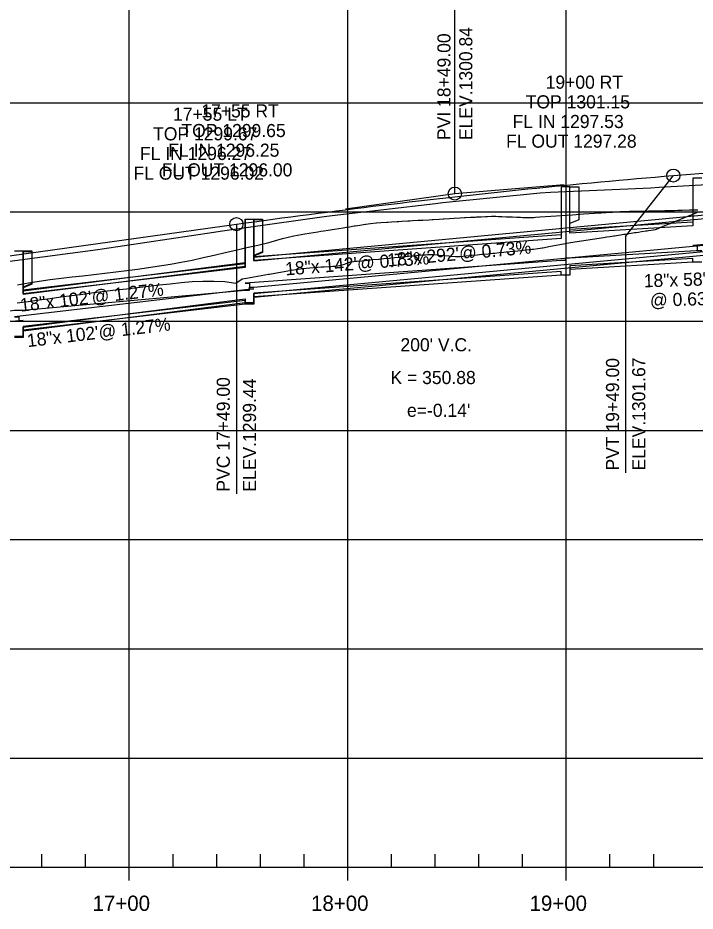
# Model space of a CAD drawing. Extents: x 670877 to 686811, y 705985 to 708501.
# Drawn here: x 685126.3 to 685436.3, y 707872.7 to 708281.7 of the extents above; entities that cross this region are included whole.
import ezdxf

# ---------------------------------------------------------------- set-up
doc = ezdxf.new("R2010")
doc.units = 0
for name, color, linetype in [('30', 7, 'Continuous'), ('37', 7, 'Continuous'), ('DRAINAGE_HGL LEFT', 7, 'Continuous'), ('DRAINAGE_HGL RIGHT', 7, 'Continuous'), ('Profile Drainage Annot Left', 7, 'Continuous'), ('Profile Drainage Annot Right', 7, 'Continuous'), ('R_Drainage Extensions_LEFT', 7, 'Continuous'), ('R_Drainage Extensions_RIGHT', 7, 'Continuous'), ('R_Drainage LEFT', 7, 'Continuous'), ('R_Drainage RIGHT', 7, 'Continuous'), ('R_Exist Surface', 7, 'Continuous'), ('R_Profile Work Left', 7, 'Continuous'), ('R_Profile Work Right', 7, 'Continuous'), ('R_Vert Alg', 7, 'Continuous'), ('R_Vert Alg Annot', 7, 'Continuous')]:
    doc.layers.add(name, color=color, linetype=linetype)

msp = doc.modelspace()

# ---------------------------------------------------------------- linework, layer by layer
at = {"layer": '37'}
for p, q in [((685177.28, 707892.85), (685177.28, 708492.85)), ((685277.28, 707892.85), (685277.28, 708492.85)), ((685377.28, 707892.85), (685377.28, 708492.85)), ((684477.28, 708242.85), (686777.28, 708242.85)), ((684477.28, 708192.85), (686777.28, 708192.85)), ((684477.28, 708142.85), (686777.28, 708142.85)), ((684477.28, 708092.85), (686777.28, 708092.85)), ((684477.28, 708042.85), (686777.28, 708042.85)), ((684477.28, 707992.85), (686777.28, 707992.85)), ((684477.28, 707942.85), (686777.28, 707942.85)), ((685137.28, 707892.85), (685137.28, 707898.85)), ((685157.28, 707892.85), (685157.28, 707898.85)), ((685197.28, 707892.85), (685197.28, 707898.85)), ((685217.28, 707892.85), (685217.28, 707898.85)), ((685237.28, 707892.85), (685237.28, 707898.85)), ((685257.28, 707892.85), (685257.28, 707898.85)), ((685297.28, 707892.85), (685297.28, 707898.85)), ((685317.28, 707892.85), (685317.28, 707898.85)), ((685337.28, 707892.85), (685337.28, 707898.85)), ((685357.28, 707892.85), (685357.28, 707898.85)), ((685397.28, 707892.85), (685397.28, 707898.85)), ((685417.28, 707892.85), (685417.28, 707898.85)), ((684477.28, 707892.85), (686777.28, 707892.85)), ((685177.28, 707886.85), (685177.28, 707892.85)), ((685277.28, 707886.85), (685277.28, 707892.85)), ((685377.28, 707886.85), (685377.28, 707892.85))]:
    msp.add_line(p, q, dxfattribs=at)
at = {"layer": 'DRAINAGE_HGL LEFT'}
msp.add_lwpolyline([(684855.2, 708111.48), (684875.01, 708112.97), (684877.28, 708112.97), (684877.28, 708115), (684879.28, 708115), (685124.73, 708147.9), (685126.73, 708147.9), (685126.73, 708147.9), (685128.73, 708147.9), (685230.25, 708157.07), (685232.25, 708157.07), (685232.25, 708158.42), (685234.25, 708158.42), (685525.17, 708185.62), (685527.18, 708185.62), (685527.18, 708186.58), (685529.23, 708186.58), (685617.8, 708197.78), (685619.52, 708197.78)], dxfattribs=at)
at = {"layer": 'DRAINAGE_HGL RIGHT'}
msp.add_lwpolyline([(685566.98, 708188.74), (685568.98, 708188.74), (685568.98, 708188.74), (685565, 708188.74), (685435.23, 708177.54), (685437.24, 708177.54), (685437.24, 708175.27), (685439.26, 708175.27), (685378.95, 708171.67), (685376.97, 708171.67), (685376.97, 708170.59), (685375, 708170.59), (685230.25, 708160.29), (685232.25, 708160.29), (685232.25, 708157.7), (685234.25, 708157.7), (685124.73, 708144.8), (685126.73, 708144.8), (685126.73, 708143.15), (685128.73, 708143.15), (684875.28, 708121.55)], dxfattribs=at)
at = {"layer": 'R_Drainage Extensions_LEFT'}
for points in [[(685234.25, 708189.55), (685238.25, 708189.55), (685238.25, 708174.55), (685234.25, 708172.88), (685234.25, 708189.55)], [(685128.73, 708175.11), (685132.73, 708175.11), (685132.73, 708160.11), (685128.73, 708158.45), (685128.73, 708175.11)]]:
    msp.add_lwpolyline(points, dxfattribs=at)
at = {"layer": 'R_Drainage Extensions_RIGHT'}
for points in [[(685378.97, 708204.29), (685382.97, 708204.29), (685382.97, 708189.29), (685378.97, 708187.63), (685378.97, 708204.29)], [(685234.25, 708189.35), (685238.25, 708189.35), (685238.25, 708174.35), (685234.25, 708172.68), (685234.25, 708189.35)], [(685128.73, 708174.81), (685132.73, 708174.81), (685132.73, 708159.81), (685128.73, 708158.15), (685128.73, 708174.81)]]:
    msp.add_lwpolyline(points, dxfattribs=at)
at = {"layer": 'R_Drainage LEFT'}
for points in [[(685234.25, 708172.21), (685525.15, 708199.41)], [(685234.25, 708170.55), (685525.15, 708197.75)], [(685230.25, 708168.05), (685230.25, 708189.55)], [(685230.25, 708189.55), (685234.25, 708189.55)], [(685234.25, 708189.55), (685234.25, 708170.55)], [(685234.25, 708155.55), (685525.15, 708182.75)], [(685234.25, 708153.88), (685525.15, 708181.08)], [(685124.73, 708175.11), (685128.73, 708175.11)], [(685128.73, 708175.11), (685128.73, 708155.15)], [(685128.73, 708156.81), (685230.25, 708169.71)], [(685128.73, 708155.15), (685230.25, 708168.05)], [(685128.73, 708140.15), (685230.25, 708153.05)], [(685230.25, 708153.05), (685230.25, 708151.38)], [(685234.25, 708151.38), (685234.25, 708155.55)], [(685128.73, 708138.48), (685230.25, 708151.38)], [(685230.25, 708151.38), (685234.25, 708151.38)], [(685128.73, 708135.98), (685128.73, 708140.15)], [(685124.73, 708135.98), (685128.73, 708135.98)]]:
    msp.add_lwpolyline(points, dxfattribs=at)
at = {"layer": 'R_Drainage RIGHT'}
for points in [[(685439.25, 708208.25), (685435.23, 708208.25)], [(685435.23, 708208.25), (685435.23, 708186.51)], [(685378.97, 708204.35), (685374.97, 708204.35)], [(685374.97, 708204.35), (685374.97, 708180.65)], [(685378.97, 708183.15), (685378.97, 708204.35)], [(685234.25, 708189.35), (685230.25, 708189.35)], [(685230.25, 708189.35), (685230.25, 708167.38)], [(685234.25, 708170.63), (685234.25, 708189.35)], [(685435.23, 708188.17), (685378.97, 708184.82)], [(685435.23, 708186.51), (685378.97, 708183.15)], [(685374.97, 708182.31), (685234.25, 708172.3)], [(685374.97, 708180.65), (685234.25, 708170.63)], [(685128.73, 708174.95), (685124.73, 708174.95)], [(685128.73, 708155.42), (685128.73, 708174.95)], [(685230.25, 708169.04), (685128.73, 708157.09)], [(685435.23, 708171.51), (685378.97, 708168.15)], [(685435.23, 708169.84), (685378.97, 708166.48)], [(685435.23, 708169.84), (685435.23, 708171.51)], [(685439.25, 708169.84), (685435.23, 708169.84)], [(685230.25, 708167.38), (685128.73, 708155.42)], [(685374.97, 708165.65), (685234.25, 708155.63)], [(685374.97, 708163.98), (685374.97, 708165.65)], [(685378.97, 708168.15), (685378.97, 708163.98)], [(685374.97, 708163.98), (685234.25, 708153.97)], [(685378.97, 708163.98), (685374.97, 708163.98)], [(685230.25, 708152.38), (685128.73, 708140.42)], [(685230.25, 708150.71), (685230.25, 708152.38)], [(685234.25, 708155.63), (685234.25, 708150.71)], [(685230.25, 708150.71), (685128.73, 708138.75)], [(685234.25, 708150.71), (685230.25, 708150.71)], [(685128.73, 708140.42), (685128.73, 708135.44)], [(685128.73, 708135.44), (685124.73, 708135.44)]]:
    msp.add_lwpolyline(points, dxfattribs=at)
at = {"layer": 'R_Exist Surface'}
msp.add_lwpolyline([(685112.1, 708168.96), (685162.81, 708175.65), (685164.92, 708175.96), (685215.99, 708183.62), (685218.83, 708184.02), (685266.46, 708190.74), (685270.16, 708191.22), (685317.41, 708196.75), (685320.79, 708197.2), (685365.31, 708201.6), (685370, 708201.88), (685416.05, 708203.83), (685419.8, 708204.14), (685461.21, 708206.48), (685467.7, 708207.16), (685497.2, 708211.08), (685499, 708211.2), (685550.57, 708215), (685552.14, 708215.26), (685552.65, 708215.45), (685556.89, 708215.85), (685597.33, 708219.75), (685604.44, 708220.24), (685639.36, 708224.31)], dxfattribs=at)
at = {"layer": 'R_Profile Work Left'}
msp.add_lwpolyline([(685126, 708151.29), (685131, 708151.92), (685136, 708152.59), (685141, 708153.26), (685146, 708153.93), (685151, 708154.59), (685156, 708155.26), (685161, 708155.93), (685166, 708156.56), (685171, 708157.14), (685176, 708157.72), (685181, 708158.29), (685186, 708158.87), (685191, 708159.45), (685196, 708160.02), (685201, 708160.6), (685206, 708161.06), (685211, 708161.1), (685215.99, 708161.14), (685220.99, 708161.07), (685225.98, 708160.26), (685228.99, 708162.2), (685230.99, 708162.56), (685235.99, 708163.44), (685240.99, 708164.33), (685240.99, 708164.33), (685241.29, 708164.38), (685241.51, 708164.41), (685241.51, 708164.42), (685242.28, 708164.55), (685246.51, 708165.29), (685251.51, 708166.16), (685256.51, 708167.04), (685261.51, 708167.46), (685261.51, 708167.46), (685263.62, 708167.6), (685265.1, 708167.69), (685266.51, 708167.78), (685268.63, 708167.92), (685270.42, 708168.03), (685271.51, 708168.1), (685273.65, 708168.3), (685275.73, 708169.01), (685276.51, 708169.27), (685277.28, 708169.54), (685278.66, 708170.01), (685281.04, 708170.3), (685281.51, 708170.34), (685283.68, 708170.55), (685286.35, 708170.8), (685286.51, 708170.81), (685288.69, 708171.02), (685291.51, 708171.28), (685291.66, 708171.3), (685293.7, 708171.49), (685296.51, 708171.75), (685296.97, 708171.8), (685298.71, 708171.96), (685301.51, 708172.22), (685302.27, 708172.29), (685303.72, 708172.43), (685306.51, 708172.69), (685307.57, 708172.79), (685308.72, 708172.9), (685311.51, 708173.16), (685312.87, 708173.29), (685313.72, 708173.37), (685316.51, 708173.32), (685318.16, 708173.17), (685318.72, 708173.12), (685321.51, 708172.87), (685323.45, 708172.7), (685323.72, 708172.67), (685326.51, 708172.43), (685328.71, 708172.46), (685328.74, 708172.46), (685331.51, 708172.74), (685333.69, 708172.96), (685334.02, 708173), (685336.51, 708173.25), (685338.68, 708173.46), (685339.3, 708173.53), (685341.51, 708173.75), (685343.65, 708173.96), (685344.57, 708174.06), (685346.51, 708174.25), (685348.63, 708174.47), (685349.84, 708174.59), (685351.51, 708174.76), (685353.59, 708174.96), (685355.1, 708175.12), (685356.51, 708175.26), (685358.55, 708175.46), (685360.36, 708175.65), (685361.51, 708175.76), (685362.28, 708175.84), (685364.28, 708176.05), (685365.28, 708176.24), (685366.28, 708176.42), (685366.51, 708176.47), (685367.28, 708176.61), (685369.28, 708176.98), (685374.28, 708177.9), (685379.28, 708178.83), (685384.28, 708179.67), (685389.28, 708180.44), (685394.28, 708181.2), (685395.79, 708181.43), (685397.28, 708181.66), (685398.97, 708181.92), (685399.28, 708181.96), (685400.34, 708182.13), (685402.16, 708182.4), (685403.69, 708182.64), (685404.28, 708182.73), (685405.35, 708182.89), (685407.04, 708183.15), (685408.55, 708183.38), (685409.28, 708183.49), (685410.4, 708183.66), (685411.75, 708183.87), (685413.76, 708184.18), (685414.28, 708184.26), (685414.95, 708184.36), (685417.13, 708184.69), (685418.16, 708184.87), (685419.28, 708185.32), (685420.5, 708185.82), (685421.37, 708186.18), (685423.87, 708187.2), (685424.28, 708187.36), (685424.58, 708187.49), (685426.28, 708188.18), (685427.25, 708188.57), (685427.8, 708188.8), (685429.28, 708189.4), (685430.63, 708189.95), (685431.01, 708190.11), (685434.01, 708191.33), (685434.23, 708191.42), (685434.28, 708191.44), (685434.28, 708191.44), (685437.39, 708192.7)], dxfattribs=at)
at = {"layer": 'R_Profile Work Right'}
msp.add_lwpolyline([(685126.08, 708159.52), (685131.08, 708160.33), (685136.08, 708161.14), (685141.08, 708161.91), (685146.08, 708162.5), (685151.08, 708163.09), (685156.08, 708163.68), (685161.08, 708164.27), (685166.08, 708164.86), (685171.08, 708165.45), (685176.07, 708166.04), (685181.07, 708166.7), (685186.07, 708167.41), (685191.07, 708168.13), (685196.08, 708168.97), (685201.08, 708169.82), (685206.08, 708170.82), (685211.08, 708171.96), (685216.08, 708173.11), (685221.08, 708174.25), (685226.09, 708175.39), (685229.09, 708176.08), (685231.09, 708176.53), (685236.09, 708177.68), (685241.09, 708178.82), (685241.09, 708178.83), (685242.23, 708179.11), (685247.38, 708180.74), (685252.52, 708181.98), (685257.64, 708182.83), (685257.64, 708182.83), (685263.54, 708183.77), (685264.97, 708184), (685266.32, 708184.22), (685268.36, 708184.55), (685270.07, 708184.83), (685271.12, 708185), (685273.17, 708185.33), (685275.17, 708185.65), (685275.92, 708185.77), (685276.66, 708185.89), (685277.99, 708186.1), (685280.27, 708186.46), (685280.72, 708186.53), (685282.8, 708186.86), (685285.37, 708187.27), (685285.52, 708187.29), (685287.62, 708187.62), (685290.32, 708187.92), (685290.47, 708187.93), (685292.43, 708188.05), (685295.12, 708188.21), (685295.56, 708188.24), (685297.23, 708188.34), (685299.92, 708188.49), (685300.65, 708188.54), (685302.04, 708188.62), (685304.71, 708188.77), (685305.73, 708188.83), (685306.83, 708188.89), (685309.5, 708189.04), (685310.81, 708189.12), (685311.63, 708189.16), (685314.3, 708189.31), (685315.88, 708189.39), (685316.42, 708189.42), (685319.09, 708189.57), (685320.96, 708189.66), (685321.21, 708189.68), (685323.88, 708189.84), (685325.99, 708189.97), (685326.02, 708189.97), (685328.68, 708190.13), (685330.77, 708190.25), (685331.09, 708190.27), (685333.47, 708190.4), (685335.55, 708190.52), (685336.15, 708190.56), (685338.26, 708190.68), (685340.32, 708190.79), (685341.2, 708190.84), (685343.06, 708190.94), (685345.08, 708190.87), (685346.24, 708190.82), (685347.83, 708190.76), (685349.82, 708190.68), (685351.27, 708190.63), (685352.61, 708190.57), (685354.56, 708190.49), (685356.32, 708190.42), (685357.44, 708190.38), (685358.19, 708190.35), (685360.18, 708190.26), (685361.18, 708190.28), (685362.18, 708190.35), (685362.41, 708190.37), (685363.18, 708190.42), (685365.18, 708190.56), (685370.18, 708190.9), (685375.18, 708191.25), (685380.18, 708191.6), (685385.18, 708191.94), (685390.18, 708192.29), (685391.7, 708192.4), (685393.26, 708192.5), (685395.04, 708192.62), (685395.36, 708192.64), (685396.48, 708192.7), (685398.39, 708192.8), (685400.08, 708192.9), (685400.73, 708192.93), (685401.92, 708192.99), (685403.79, 708193.09), (685405.45, 708193.12), (685406.25, 708193.14), (685407.49, 708193.16), (685408.98, 708193.19), (685411.21, 708193.24), (685411.78, 708193.25), (685412.53, 708193.27), (685414.93, 708193.32), (685416.08, 708193.34), (685417.31, 708193.37), (685418.66, 708193.4), (685419.63, 708193.42), (685422.4, 708193.49), (685422.85, 708193.5), (685423.19, 708193.51), (685425.07, 708193.55), (685426.15, 708193.58), (685426.76, 708193.59), (685428.4, 708193.63), (685429.9, 708193.67), (685430.33, 708193.68), (685433.66, 708193.76), (685433.9, 708193.77), (685433.96, 708193.77), (685433.96, 708193.77), (685437.42, 708193.86)], dxfattribs=at)
at = {"layer": 'R_Vert Alg'}
for p, q in [((685426.28, 708209.51), (685614.19, 708225.05)), ((685404.45, 708181.65), (685426.28, 708209.51)), ((685326.28, 708201.25), (685376.28, 708205.38)), ((685276.28, 708194.25), (685326.28, 708201.25)), ((685006.28, 708156.45), (685226.28, 708187.25))]:
    msp.add_line(p, q, dxfattribs=at)
msp.add_lwpolyline([(685226.28, 708187.25), (685230.44, 708187.83), (685234.61, 708188.4), (685238.78, 708188.98), (685242.94, 708189.54), (685247.11, 708190.1), (685251.28, 708190.66), (685255.44, 708191.21), (685259.61, 708191.76), (685263.78, 708192.3), (685267.94, 708192.83), (685272.11, 708193.36), (685276.28, 708193.89), (685280.44, 708194.41), (685284.61, 708194.93), (685288.78, 708195.44), (685292.94, 708195.94), (685297.11, 708196.45), (685301.28, 708196.94), (685305.44, 708197.43), (685309.61, 708197.92), (685313.78, 708198.4), (685317.94, 708198.88), (685322.11, 708199.35), (685330.44, 708200.28), (685334.61, 708200.73), (685338.78, 708201.18), (685342.94, 708201.63), (685347.11, 708202.07), (685351.28, 708202.51), (685355.44, 708202.94), (685359.61, 708203.37), (685363.78, 708203.79), (685367.94, 708204.2), (685372.11, 708204.62), (685376.28, 708205.02), (685380.44, 708205.42), (685384.61, 708205.82), (685388.78, 708206.21), (685392.94, 708206.6), (685397.11, 708206.98), (685401.28, 708207.36), (685405.44, 708207.73), (685409.61, 708208.1), (685413.78, 708208.46), (685417.94, 708208.82), (685422.11, 708209.17), (685426.28, 708209.51)], dxfattribs=at)
for centre in [(685426.28, 708209.51), (685326.28, 708201.25), (685226.28, 708187.25)]:
    msp.add_circle(centre, 3, dxfattribs=at)
at = {"layer": 'R_Vert Alg Annot'}
for p, q in [((685326.28, 708201.25), (685326.28, 708300.77)), ((685226.28, 708187.25), (685226.28, 708063.8)), ((685404.45, 708181.65), (685404.45, 708073.46))]:
    msp.add_line(p, q, dxfattribs=at)

# ---------------------------------------------------------------- texts
at = {"layer": '30'}
for s, p in [('17+00', (685160.47, 707872.85)), ('18+00', (685260.47, 707872.85)), ('19+00', (685360.47, 707872.85))]:
    msp.add_text(s, height=7, dxfattribs=at).set_placement(p)
at = {"layer": 'Profile Drainage Annot Left'}
for s, p in [('17+55 LT', (685197.28, 708234.63)), ('TOP 1299.67', (685188.16, 708225.63)), ('FL IN 1296.27', (685182.16, 708216.63)), ('FL OUT 1296.02', (685179.17, 708207.63))]:
    msp.add_text(s, height=6, dxfattribs=at).set_placement(p)
for s, rotation, p in [('18"x 292\'@ 0.73%', 5.2619, (685295.66, 708167.79)), ('18"x 102\'@ 1.27%', 6.6885, (685130.8, 708130.94))]:
    msp.add_text(s, height=6, rotation=rotation, dxfattribs=at).set_placement(p)
at = {"layer": 'Profile Drainage Annot Right'}
for s, p in [('19+00 RT', (685367.82, 708249.27)), ('TOP 1301.15', (685358.71, 708240.27)), ('17+55 RT', (685210.23, 708236.13)), ('FL IN 1297.53', (685352.71, 708231.27)), ('TOP 1299.65', (685201.12, 708227.13)), ('FL OUT 1297.28', (685349.72, 708222.27)), ('FL IN 1296.25', (685195.12, 708218.13)), ('FL OUT 1296.00', (685192.16, 708209.13))]:
    msp.add_text(s, height=6, dxfattribs=at).set_placement(p)
for s, rotation, p in [('18"x 142\'@ 0.73%', 4.4507, (685248.88, 708163.78)), ('18"x 58\'', 1.7647, (685412.83, 708158.33)), ('18"x 102\'@ 1.27%', 6.448, (685127.61, 708147.18)), ('@ 0.63%', 1.7647, (685415.66, 708149.41))]:
    msp.add_text(s, height=6, rotation=rotation, dxfattribs=at).set_placement(p)
at = {"layer": 'R_Vert Alg Annot'}
for s, p in [('ELEV.1300.84', (685334.28, 708225.77)), ('PVI 18+49.00', (685324.28, 708225.77)), ('PVT 19+49.00', (685401.45, 708074.46)), ('ELEV.1301.67', (685413.45, 708074.46)), ('PVC 17+49.00', (685223.28, 708064.8)), ('ELEV.1299.44', (685235.28, 708064.8))]:
    msp.add_text(s, height=6, rotation=90, dxfattribs=at).set_placement(p)
for s, p in [("200' V.C.", (685301.38, 708129.05)), ('K = 350.88', (685296.8, 708114.05)), ("e=-0.14'", (685304.38, 708099.05))]:
    msp.add_text(s, height=6, dxfattribs=at).set_placement(p)

doc.saveas('drawing.dxf')
